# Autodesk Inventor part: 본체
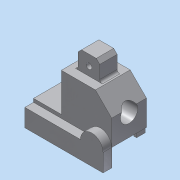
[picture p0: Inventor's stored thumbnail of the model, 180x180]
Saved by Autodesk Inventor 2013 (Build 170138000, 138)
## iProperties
Created: 2016-11
Part Number: 본체
Material: 알루미늄 6061
Document SubType Name: Modeling
Designer: dgall
Density: 1 g/cm^3
Author: dgall
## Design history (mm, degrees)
sketch "스케치2"
  geometry: L1 (-58, -35.242)-(-58, -5.991); L2 (-39.251, 12.758)-(0, 12.758); L3 (0, 12.758)-(0, -31.242); L4 (-58, -5.991)-(0, -5.991); L5 (-58, -5.991)-(-39.251, 12.758); L6 (0, -31.242)-(32, -31.242); L7 (32, -31.242)-(32, -35.242); L8 (-58, -35.242)-(32, -35.242); 1 further point
  constraints: 16 end point, 4 perpendicular, 2 parallel, 1 point on line, 1 vertical
  dimensions: "d9" = 0 distance from line of point (0, 0) L3; "d10" = 58 distance between parallel lines of L1 L3; "d11" = 48 vertical distance of L1.start L2.start; "d13" = 45 deg angle of L5 L2; "d14" = 90 distance from line of L6.end L1; "d15" = 4 distance of L7.end L6.end
extrude "돌출1" new body sketch "스케치2" distance "d16" = 40; taper "d17" = 0 deg
sketch "스케치3"
  geometry: L1 (44, 0)-(44, 40) reference; C1 r 14.5 at (20, 20); 1 further point
  constraints: 1 centre point
  dimensions: "d18" = 24 distance from line of C1.centre L1; "d19" = 29 diameter of C1
extrude "돌출2" cut sketch "스케치3" distance "d20" = 7; taper "d21" = 0 deg
sketch "스케치4"
  geometry: C1 r 14.5 at (0, 0) reference; C2 r 10 at (0, 0); 1 further point
  constraints: 1 centre point, 1 coincident
  dimensions: "d22" = 20 diameter of C2
extrude "돌출3" cut sketch "스케치4" stored distance "d24" = 7; taper "d25" = 0 deg
node "작업 평면1"
sketch "스케치5"
  geometry: L1 (0, 12.758)-(-39.251, 12.758) reference; L2 (-34.255, 12.758)-(-34.255, 34.758); L3 (-34.255, 34.758)-(-9.255, 34.758); L4 (-9.255, 34.758)-(-9.255, 12.758); L5 (-58, -35.242)-(32, -35.242) reference; 1 further point
  constraints: 6 end point, 3 perpendicular, 2 point on line
  dimensions: "d26" = 25 distance between parallel lines of L4 L2; "d28" = 70 distance between parallel lines of L3 L5
extrude "돌출4" join sketch "스케치5" stored distance "d29" = 20; taper "d30" = 0 deg
sketch "스케치6"
  geometry: C1 r 4 at (21.755, -22.897); 1 further point
  constraints: 1 centre point
  dimensions: "d31" = 8 diameter of C1
hole "구멍1" sketch "스케치6" at (21.755, -22.897) diameter "d33" = 6.647; stored, may be unused: countersink angle "d37" = 90 deg, drill point angle "d39" = 118 deg; dims "d34" = 6, "d35" = 4, "d36" = 2, "d38" = 8
chamfer "모따기1" distance "d40" = 4; stored, may be unused: second distance "d41" = 2, angle "d42" = 45 deg
fillet "모깎기1" dims "d43" = 3
node "작업 평면2"
sketch "스케치7"
  geometry: L1 (46.63, 37.365)-(46.63, 51.242); L2 (46.63, 51.242)-(43.63, 51.242); L3 (43.63, 51.242)-(43.63, 44.242); L4 (-32, 35.242)-(-32, 31.242) reference; L5 (43.63, 44.242)-(22.883, 44.242); L6 (-32, 31.242)-(0, 31.242) reference; L7 (22.883, 44.242)-(22.883, 50.242); L8 (22.883, 50.242)-(-32, 50.242); L9 (-32, 50.242)-(-32, 35.242); L10 (58, 35.242)-(-32, 35.242) reference; L11 (20.804, 35.242)-(-32, 35.242); A1 r 13 centre (33.63, 37.365) between (20.804, 35.242) and (46.63, 37.365); 1 further point
  constraints: 16 end point, 5 perpendicular, 2 point on circle, 1 centre point, 1 collinear, 1 parallel, 1 tangent, 1 vertical
  dimensions: "d47" = 26 diameter of A1; "d50" = 7 vertical distance of L3.end L1.end; "d51" = 3 distance between parallel lines of L3 L1
extrude "돌출5" join sketch "스케치7" distance "d55" = 10; taper "d56" = 0 deg
node "작업 평면3"
sketch "스케치8"
  geometry: L1 (58, -35.242)-(58, -55.626); L2 (58, -5.991)-(58, -35.242) reference; L3 (-32, -35.242)-(-32, -50.242) reference; L4 (32, -35.242)-(-32, -35.242); L5 (-32, -35.242)-(-32, -55.626); L6 (-32, -55.626)-(58, -55.626); A1 r 13 centre (45, -35.242) between (58, -35.242) and (32, -35.242); 1 further point
  constraints: 8 end point, 2 perpendicular, 2 point on circle, 1 centre point, 1 tangent
  dimensions: "d58" = 26 diameter of A1; "d60" = 0 vertical distance of L2.end L4.start; "d61" = 0 distance from line of L2.end L1
extrude "돌출6" join sketch "스케치8" distance "d63" = 10; taper "d64" = 0 deg
node "작업 평면4"
sketch "스케치9"
  geometry: L1 (41.592, 2.84)-(8.408, 2.84); L2 (8.408, 2.84)-(8.408, 7.644); L3 (8.408, 7.644)-(41.592, 7.644); L4 (41.592, 7.644)-(41.592, 2.84); L5 (41.592, 5.242)-(8.408, 5.242); L6 (25, 2.84)-(25, 7.644); L7 (0, -12.758)-(39.251, -12.758) reference; L8 (0, 31.242)-(0, -12.758) reference; 1 further point
  constraints: 4 end point, 4 midpoint, 2 other
  dimensions: "d66" = 18 distance from line of L5.start L7; "d67" = 25 distance from line of L6.start L8
feature "엠보싱1" sketch "스케치9" dims "d68" = 0.5, "d69" = 0
node "솔리드1"
other parameters: "d65" = 71.5
